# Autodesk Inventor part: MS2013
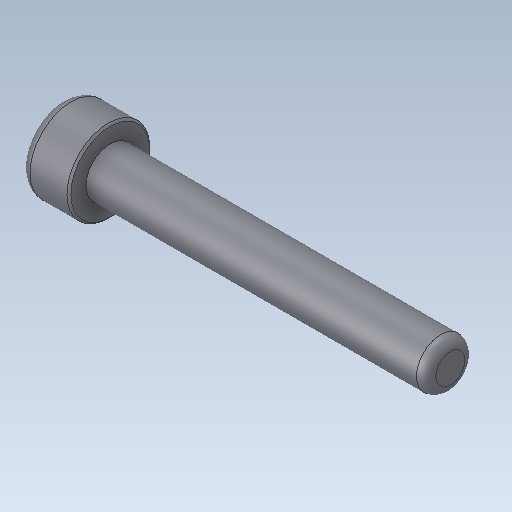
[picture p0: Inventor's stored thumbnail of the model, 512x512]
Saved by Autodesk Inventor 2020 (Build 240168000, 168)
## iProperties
Created: 2015-11
Part Number: MS2013
Material: Ogólny
Document SubType Name: Modeling
Designer: Tomasz
Density: 1 g/cm^3
Appearance: Domyślna
Sending System: SolidWorks 2017
Last Author: Tomasz
Last Saved: 2017-09-17
Author: Tomasz
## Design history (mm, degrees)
feature "Imported1"
node "Bryła1"
